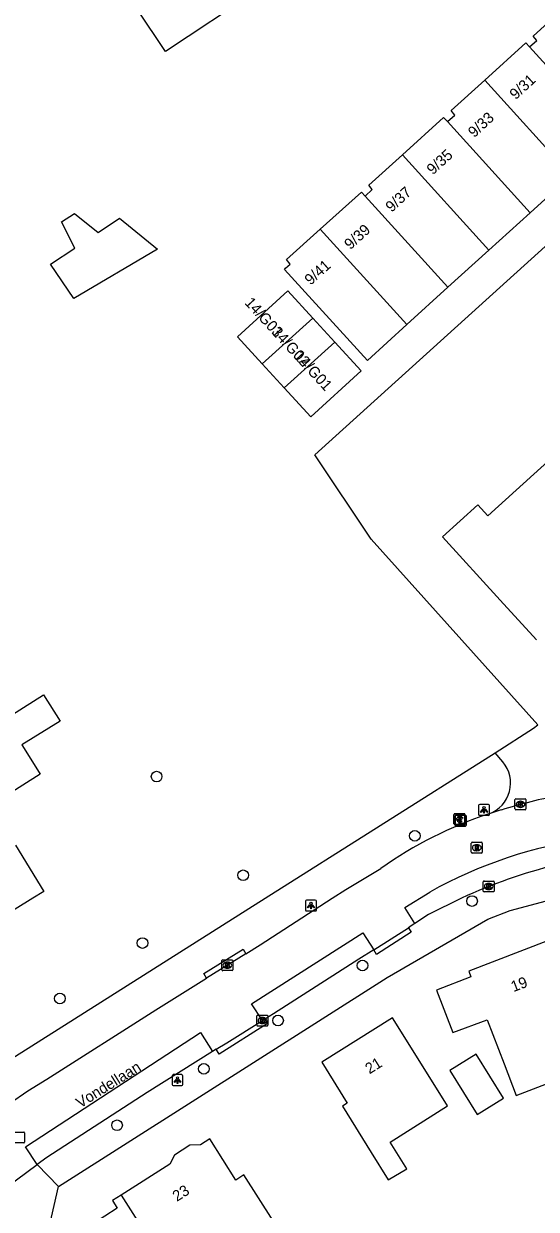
# Model space of a CAD drawing. Extents: x 161354 to 161876, y 382161 to 382804.
# Drawn here: x 161596.3 to 161643.4, y 382471.4 to 382580.4 of the extents above; entities that cross this region are included whole.
import ezdxf

# ---------------------------------------------------------------- set-up
doc = ezdxf.new("R2010")
doc.units = 0
for name, color, linetype in [('IMGEO_Betaalautomaat', 7, 'Continuous'), ('IMGEO_Boom', 7, 'Continuous'), ('IMGEO_Kolk', 7, 'Continuous'), ('IMGEO_Lichtpunt', 7, 'Continuous'), ('IMGEO_Openbare_ruimte_label', 7, 'Continuous'), ('IMGEO_Pand', 7, 'Continuous'), ('IMGEO_Pand_nummerreeks', 7, 'Continuous'), ('IMGEO_Pand_vergunning_verleend', 7, 'Continuous'), ('IMGEO_Parkeervlak_gesloten', 7, 'Continuous'), ('IMGEO_Rijbaan_lokaal_open', 7, 'Continuous'), ('IMGEO_Rioolput', 7, 'Continuous'), ('IMGEO_Voetpad_open', 7, 'Continuous')]:
    doc.layers.add(name, color=color, linetype=linetype)

msp = doc.modelspace()

# ---------------------------------------------------------------- linework, layer by layer
at = {"layer": 'IMGEO_Betaalautomaat'}
for p, q in [((161635.9, 382507.75), (161636.74, 382507.75)), ((161636.74, 382507.75), (161635.9, 382507.75)), ((161635.82, 382506.83), (161635.82, 382507.67)), ((161635.82, 382507.67), (161635.82, 382506.83)), ((161636.75, 382506.75), (161635.91, 382506.75)), ((161635.91, 382506.75), (161636.75, 382506.75)), ((161635.94, 382506.7), (161635.94, 382507.54)), ((161635.94, 382507.54), (161635.94, 382506.7)), ((161636.02, 382507.62), (161636.86, 382507.62)), ((161636.86, 382507.62), (161636.02, 382507.62)), ((161636.11, 382507.22), (161636.11, 382507.29)), ((161636.23, 382507.29), (161636.23, 382507.22)), ((161636.23, 382507.08), (161636.23, 382507.15)), ((161636.35, 382507.15), (161636.35, 382507.08)), ((161636.49, 382507.56), (161636.47, 382507.46)), ((161636.47, 382507.05), (161636.49, 382506.97)), ((161636.6, 382507.43), (161636.59, 382507.33)), ((161636.59, 382506.92), (161636.61, 382506.83)), ((161636.82, 382507.68), (161636.82, 382506.84)), ((161636.82, 382506.84), (161636.82, 382507.68)), ((161636.94, 382507.55), (161636.94, 382506.71)), ((161636.94, 382506.71), (161636.94, 382507.55)), ((161636.87, 382506.62), (161636.03, 382506.62)), ((161636.03, 382506.62), (161636.87, 382506.62))]:
    msp.add_line(p, q, dxfattribs=at)
for points in [[(161636.11, 382507.29), (161636.04, 382507.29), (161636.04, 382507.35), (161636.12, 382507.35)], [(161636.11, 382507.15), (161636.04, 382507.15), (161636.04, 382507.22), (161636.11, 382507.22)], [(161636.23, 382507.15), (161636.16, 382507.15), (161636.16, 382507.22), (161636.24, 382507.22)], [(161636.23, 382507.02), (161636.16, 382507.02), (161636.16, 382507.08), (161636.23, 382507.08)], [(161636.24, 382507.35), (161636.39, 382507.35), (161636.39, 382507.29), (161636.23, 382507.29)], [(161636.23, 382507.22), (161636.39, 382507.22), (161636.39, 382507.15), (161636.24, 382507.15)], [(161636.36, 382507.22), (161636.51, 382507.22), (161636.51, 382507.15), (161636.35, 382507.15)], [(161636.35, 382507.08), (161636.51, 382507.08), (161636.51, 382507.02), (161636.36, 382507.02)]]:
    msp.add_lwpolyline(points, dxfattribs=at)
for centre, radius, start, end in [((161635.9, 382507.68), 0.0779, 92.4484, 184.2845), ((161635.9, 382507.68), 0.0779, 92.4484, 184.2845), ((161636.75, 382507.68), 0.0779, 2.4484, 94.2845), ((161636.75, 382507.68), 0.0779, 2.4484, 94.2845), ((161635.9, 382506.83), 0.0779, 182.4484, 274.2845), ((161635.9, 382506.83), 0.0779, 182.4484, 274.2845), ((161636.02, 382507.54), 0.0779, 92.4484, 184.2845), ((161636.02, 382507.54), 0.0779, 92.4484, 184.2845), ((161636.02, 382506.7), 0.0779, 182.4484, 274.2845), ((161636.02, 382506.7), 0.0779, 182.4484, 274.2845), ((161636.37, 382507.2), 0.267, 191.8096, 297.0389), ((161636.4, 382507.28), 0.293, 73.014, 165.0139), ((161636.49, 382507.07), 0.267, 191.8096, 297.0389), ((161636.41, 382507.29), 0.179, 69.3236, 159.5683), ((161636.52, 382507.14), 0.293, 73.014, 165.0139), ((161636.41, 382507.22), 0.179, 202.7625, 291.8693), ((161636.53, 382507.16), 0.179, 69.3236, 159.5683), ((161636.53, 382507.08), 0.179, 202.7625, 291.8693), ((161636.75, 382506.83), 0.0779, 272.4484, 4.2845), ((161636.75, 382506.83), 0.0779, 272.4484, 4.2845), ((161636.86, 382507.54), 0.0779, 2.4484, 94.2845), ((161636.86, 382507.54), 0.0779, 2.4484, 94.2845), ((161636.86, 382506.7), 0.0779, 272.4484, 4.2845), ((161636.86, 382506.7), 0.0779, 272.4484, 4.2845)]:
    msp.add_arc(centre, radius, start, end, dxfattribs=at)
at = {"layer": 'IMGEO_Boom'}
for centre in [(161608.52, 382511.17), (161632.23, 382505.72), (161616.46, 382502.1), (161637.48, 382499.73), (161607.22, 382495.87), (161627.42, 382493.8), (161599.64, 382490.77), (161619.67, 382488.75), (161612.85, 382484.3), (161604.89, 382479.12)]:
    msp.add_circle(centre, 0.489, dxfattribs=at)
at = {"layer": 'IMGEO_Kolk'}
for p, q in [((161641.42, 382508.2), (161641.42, 382509.05)), ((161641.5, 382509.12), (161642.35, 382509.12)), ((161641.91, 382508.9), (161641.94, 382508.9)), ((161642.43, 382509.05), (161642.43, 382508.2)), ((161642.35, 382508.12), (161641.5, 382508.12)), ((161641.93, 382508.34), (161641.91, 382508.34)), ((161638.51, 382500.65), (161638.51, 382501.5)), ((161638.59, 382501.57), (161639.44, 382501.57)), ((161639, 382501.35), (161639.02, 382501.35)), ((161639.51, 382501.5), (161639.51, 382500.65)), ((161639.44, 382500.57), (161638.59, 382500.57)), ((161639.02, 382500.79), (161639, 382500.79)), ((161614.52, 382493.4), (161614.52, 382494.26)), ((161614.59, 382494.33), (161615.44, 382494.33)), ((161615, 382494.11), (161615.03, 382494.11)), ((161615.52, 382494.26), (161615.52, 382493.4)), ((161615.44, 382493.33), (161614.59, 382493.33)), ((161615.03, 382493.55), (161615, 382493.55)), ((161617.81, 382489.24), (161618.66, 382489.24)), ((161617.73, 382488.31), (161617.73, 382489.17)), ((161618.66, 382488.24), (161617.81, 382488.24)), ((161618.22, 382489.02), (161618.25, 382489.02)), ((161618.24, 382488.46), (161618.22, 382488.46)), ((161618.73, 382489.17), (161618.73, 382488.31))]:
    msp.add_line(p, q, dxfattribs=at)
for points in [[(161641.42, 382508.2), (161641.42, 382509.05)], [(161641.5, 382509.12), (161642.35, 382509.12)], [(161641.74, 382508.82), (161641.87, 382508.82), (161641.87, 382508.67), (161642, 382508.82), (161642.16, 382508.82), (161642.02, 382508.67), (161642.17, 382508.42), (161642.02, 382508.42), (161641.93, 382508.59), (161641.87, 382508.52), (161641.87, 382508.42), (161641.74, 382508.42), (161641.74, 382508.82)], [(161642.43, 382509.05), (161642.43, 382508.2)], [(161642.35, 382508.12), (161641.5, 382508.12)], [(161638.51, 382500.65), (161638.51, 382501.5)], [(161638.59, 382501.57), (161639.44, 382501.57)], [(161638.83, 382501.27), (161638.96, 382501.27), (161638.96, 382501.12), (161639.08, 382501.27), (161639.25, 382501.27), (161639.1, 382501.12), (161639.26, 382500.87), (161639.1, 382500.87), (161639.02, 382501.04), (161638.96, 382500.97), (161638.96, 382500.87), (161638.83, 382500.87), (161638.83, 382501.27)], [(161639.51, 382501.5), (161639.51, 382500.65)], [(161639.44, 382500.57), (161638.59, 382500.57)], [(161614.52, 382493.4), (161614.52, 382494.26)], [(161614.59, 382494.33), (161615.44, 382494.33)], [(161614.84, 382494.03), (161614.96, 382494.03), (161614.96, 382493.88), (161615.09, 382494.03), (161615.25, 382494.03), (161615.11, 382493.88), (161615.26, 382493.63), (161615.11, 382493.63), (161615.02, 382493.79), (161614.96, 382493.73), (161614.96, 382493.63), (161614.84, 382493.63), (161614.84, 382494.03)], [(161615.52, 382494.26), (161615.52, 382493.4)], [(161615.44, 382493.33), (161614.59, 382493.33)], [(161617.81, 382489.24), (161618.66, 382489.24)], [(161617.73, 382488.31), (161617.73, 382489.17)], [(161618.66, 382488.24), (161617.81, 382488.24)], [(161618.05, 382488.94), (161618.18, 382488.94), (161618.18, 382488.79), (161618.31, 382488.94), (161618.47, 382488.94), (161618.32, 382488.79), (161618.48, 382488.54), (161618.32, 382488.54), (161618.24, 382488.7), (161618.18, 382488.64), (161618.18, 382488.54), (161618.05, 382488.54), (161618.05, 382488.94)], [(161618.73, 382489.17), (161618.73, 382488.31)]]:
    msp.add_lwpolyline(points, dxfattribs=at)
for centre, start, end in [((161641.5, 382509.05), 91.552, 178.448), ((161641.5, 382509.05), 91.552, 178.448), ((161642.35, 382509.05), 1.552, 88.448), ((161642.35, 382509.05), 1.552, 88.448), ((161641.5, 382508.2), 181.552, 268.448), ((161641.5, 382508.2), 181.552, 268.448), ((161642.35, 382508.2), 271.552, 358.448), ((161642.35, 382508.2), 271.552, 358.448), ((161638.59, 382501.5), 91.552, 178.448), ((161638.59, 382501.5), 91.552, 178.448), ((161639.44, 382501.5), 1.552, 88.448), ((161639.44, 382501.5), 1.552, 88.448), ((161638.59, 382500.65), 181.552, 268.448), ((161638.59, 382500.65), 181.552, 268.448), ((161639.44, 382500.65), 271.552, 358.448), ((161639.44, 382500.65), 271.552, 358.448), ((161614.59, 382494.25), 91.552, 178.448), ((161614.59, 382494.25), 91.552, 178.448), ((161615.44, 382494.25), 1.552, 88.448), ((161615.44, 382494.25), 1.552, 88.448), ((161614.59, 382493.4), 181.552, 268.448), ((161614.59, 382493.4), 181.552, 268.448), ((161615.44, 382493.4), 271.552, 358.448), ((161615.44, 382493.4), 271.552, 358.448), ((161617.81, 382489.16), 91.552, 178.448), ((161617.81, 382489.16), 91.552, 178.448), ((161618.66, 382489.16), 1.552, 88.448), ((161618.66, 382489.16), 1.552, 88.448), ((161617.81, 382488.32), 181.552, 268.448), ((161617.81, 382488.32), 181.552, 268.448), ((161618.66, 382488.32), 271.552, 358.448), ((161618.66, 382488.32), 271.552, 358.448)]:
    msp.add_arc(centre, 0.0765, start, end, dxfattribs=at)
for centre, major_axis, ratio, start_param, end_param in [((161641.91, 382508.62), (-0.387, 0.002), 0.722429, 4.712389, 7.853982), ((161641.94, 382508.62), (-0.39, 0.002), 0.717154, 1.570796, 4.712389), ((161639, 382501.07), (-0.387, 0.002), 0.722429, 4.712389, 7.853982), ((161639.02, 382501.07), (-0.39, 0.002), 0.717154, 1.570796, 4.712389), ((161615, 382493.83), (-0.387, 0.002), 0.722429, 4.712389, 7.853982), ((161615.03, 382493.83), (-0.39, 0.002), 0.717154, 1.570796, 4.712389), ((161618.22, 382488.74), (-0.387, 0.002), 0.722429, 4.712389, 7.853982), ((161618.24, 382488.74), (-0.39, 0.002), 0.717154, 1.570796, 4.712389)]:
    msp.add_ellipse(centre, major_axis=major_axis, ratio=ratio, start_param=start_param, end_param=end_param, dxfattribs=at)
at = {"layer": 'IMGEO_Lichtpunt'}
for p, q in [((161638.08, 382508.51), (161638.08, 382507.7)), ((161638.08, 382508.51), (161638.08, 382507.7)), ((161638.98, 382508.6), (161638.18, 382508.6)), ((161638.98, 382508.6), (161638.18, 382508.6)), ((161639.08, 382507.7), (161639.08, 382508.51)), ((161639.08, 382507.7), (161639.08, 382508.51)), ((161638.18, 382507.61), (161638.98, 382507.61)), ((161638.18, 382507.61), (161638.98, 382507.61)), ((161622.19, 382499.72), (161622.19, 382498.91)), ((161622.19, 382499.72), (161622.19, 382498.91)), ((161623.09, 382499.82), (161622.28, 382499.82)), ((161623.09, 382499.82), (161622.28, 382499.82)), ((161623.19, 382498.91), (161623.19, 382499.72)), ((161623.19, 382498.91), (161623.19, 382499.72)), ((161622.28, 382498.82), (161623.09, 382498.82)), ((161622.28, 382498.82), (161623.09, 382498.82)), ((161610.84, 382483.77), (161610.03, 382483.77)), ((161610.84, 382483.77), (161610.03, 382483.77)), ((161609.94, 382483.67), (161609.94, 382482.87)), ((161609.94, 382483.67), (161609.94, 382482.87)), ((161610.03, 382482.77), (161610.84, 382482.77)), ((161610.03, 382482.77), (161610.84, 382482.77)), ((161610.93, 382482.87), (161610.93, 382483.67)), ((161610.93, 382482.87), (161610.93, 382483.67))]:
    msp.add_line(p, q, dxfattribs=at)
for points in [[(161638.46, 382508.17), (161638.49, 382508.15), (161638.31, 382507.88), (161638.27, 382507.91), (161638.46, 382508.17)], [(161638.56, 382508.13), (161638.6, 382508.13), (161638.6, 382507.8), (161638.56, 382507.8), (161638.56, 382508.13)], [(161638.67, 382508.15), (161638.71, 382508.17), (161638.89, 382507.91), (161638.85, 382507.88), (161638.67, 382508.15)], [(161622.56, 382499.38), (161622.6, 382499.36), (161622.42, 382499.09), (161622.38, 382499.12), (161622.56, 382499.38)], [(161622.67, 382499.34), (161622.71, 382499.34), (161622.71, 382499.01), (161622.67, 382499.01), (161622.67, 382499.34)], [(161622.78, 382499.36), (161622.81, 382499.38), (161623, 382499.12), (161622.96, 382499.09), (161622.78, 382499.36)], [(161610.31, 382483.34), (161610.35, 382483.31), (161610.16, 382483.05), (161610.12, 382483.07), (161610.31, 382483.34)], [(161610.41, 382483.29), (161610.46, 382483.29), (161610.46, 382482.97), (161610.41, 382482.97), (161610.41, 382483.29)], [(161610.52, 382483.31), (161610.56, 382483.34), (161610.75, 382483.07), (161610.71, 382483.05), (161610.52, 382483.31)]]:
    msp.add_lwpolyline(points, dxfattribs=at)
for centre in [(161638.58, 382508.31), (161622.69, 382499.52), (161610.44, 382483.47)]:
    msp.add_circle(centre, 0.0994, dxfattribs=at)
for centre, start, end in [((161638.18, 382508.51), 90, 180), ((161638.18, 382508.51), 90, 180), ((161638.98, 382508.51), 0, 90), ((161638.98, 382508.51), 0, 90), ((161638.18, 382507.7), 180, 270), ((161638.18, 382507.7), 180, 270), ((161638.98, 382507.7), 270, 0), ((161638.98, 382507.7), 270, 360), ((161622.28, 382499.72), 90, 180), ((161622.28, 382499.72), 90, 180), ((161623.09, 382499.72), 0, 90), ((161623.09, 382499.72), 0, 90), ((161622.28, 382498.91), 180, 270), ((161622.28, 382498.91), 180, 270), ((161623.09, 382498.91), 270, 0), ((161623.09, 382498.91), 270, 360), ((161610.03, 382483.67), 90, 180), ((161610.03, 382483.67), 90, 180), ((161610.84, 382483.67), 0, 90), ((161610.84, 382483.67), 0, 90), ((161610.03, 382482.87), 180, 270), ((161610.03, 382482.87), 180, 270), ((161610.84, 382482.87), 270, 0), ((161610.84, 382482.87), 270, 360)]:
    msp.add_arc(centre, 0.0946, start, end, dxfattribs=at)
at = {"layer": 'IMGEO_Pand'}
for points in [[(161617.74, 382583.42), (161609.32, 382577.81), (161601.47, 382589.62)], [(161642.76, 382578.24), (161643.43, 382578.83), (161643.1, 382579.23), (161646.19, 382582.04)], [(161638.64, 382575.19), (161642.41, 382578.62), (161642.76, 382578.24)], [(161650.36, 382569.86), (161642.76, 382578.24)], [(161635.21, 382571.38), (161635.89, 382571.98), (161635.56, 382572.39), (161638.64, 382575.19)], [(161638.64, 382575.19), (161646.58, 382566.43)], [(161631.09, 382568.33), (161634.86, 382571.76), (161635.21, 382571.38)], [(161642.81, 382563), (161635.21, 382571.38)], [(161627.66, 382564.52), (161628.32, 382565.12), (161627.99, 382565.52), (161631.09, 382568.33)], [(161639.03, 382559.57), (161631.09, 382568.33)], [(161674.64, 382567.53), (161638.94, 382535.13), (161638.01, 382536.16), (161634.76, 382533.21), (161640.06, 382527.37), (161643.39, 382523.73)], [(161646.58, 382566.43), (161642.81, 382563)], [(161623.53, 382561.48), (161627.32, 382564.9), (161627.66, 382564.52)], [(161635.26, 382556.15), (161627.66, 382564.52)], [(161642.81, 382563), (161639.03, 382559.57)], [(161631.48, 382552.71), (161627.87, 382549.43), (161620.25, 382557.79), (161620.36, 382557.89), (161620.78, 382558.27), (161620.45, 382558.7), (161623.53, 382561.48)], [(161631.48, 382552.71), (161623.53, 382561.48)], [(161639.03, 382559.57), (161635.26, 382556.15)], [(161618.22, 382549.12), (161615.95, 382551.6), (161620.57, 382555.83), (161622.87, 382553.31)], [(161635.26, 382556.15), (161631.48, 382552.71)], [(161622.87, 382553.31), (161618.22, 382549.12)], [(161622.87, 382553.31), (161624.89, 382551.1)], [(161624.89, 382551.1), (161627.3, 382548.48), (161622.68, 382544.25), (161620.24, 382546.91)], [(161620.24, 382546.91), (161624.89, 382551.1)], [(161620.24, 382546.91), (161618.22, 382549.12)], [(161588.47, 382525.14), (161594.1, 382516.15), (161598.14, 382518.68), (161599.65, 382516.26), (161596.15, 382514.08)], [(161596.15, 382514.08), (161596.37, 382513.74), (161597.84, 382511.38), (161592.68, 382508.15)], [(161595.57, 382504.88), (161598.18, 382500.62), (161597.17, 382500), (161593.88, 382497.98)], [(161645.12, 382483.24), (161645.64, 382483.44), (161645.81, 382483.51), (161645.97, 382483.1), (161649.52, 382484.47), (161648.04, 382488.31), (161647.84, 382488.23), (161646.43, 382491.89), (161649.3, 382492.99), (161647.85, 382496.77), (161644.62, 382495.52), (161644.41, 382496.06), (161637.17, 382493.28), (161637.37, 382492.75), (161634.22, 382491.54), (161635.71, 382487.65), (161638.86, 382488.81), (161640.42, 382484.76), (161641.53, 382481.86), (161645.12, 382483.24)], [(161632.83, 382484.73), (161630.19, 382488.98), (161623.68, 382484.93), (161626.02, 382481.16), (161625.57, 382480.88), (161628.21, 382476.63), (161629.77, 382474.11), (161631.49, 382475.11), (161629.95, 382477.58), (161635.23, 382480.91), (161632.83, 382484.73)], [(161635.45, 382484.14), (161637.95, 382480.1), (161640.38, 382481.61), (161637.87, 382485.64), (161635.45, 382484.14)], [(161619.13, 382465.69), (161623.02, 382464.82), (161623.73, 382468.01), (161620.2, 382468.79), (161619.22, 382470.34), (161616.54, 382474.55), (161615.79, 382474.08), (161613.39, 382477.86), (161612.54, 382477.32), (161611.58, 382477.28), (161610.17, 382476.38), (161609.73, 382475.54), (161605.26, 382472.7)], [(161605.26, 382472.7), (161604.46, 382472.19), (161604.91, 382471.49), (161602.62, 382470.03), (161601.24, 382463.88), (161602.74, 382461.53), (161601.96, 382461.04), (161603.69, 382458.32)], [(161605.26, 382472.7), (161607.62, 382468.98), (161612.38, 382467.44)]]:
    msp.add_lwpolyline(points, dxfattribs=at)
at = {"layer": 'IMGEO_Pand_vergunning_verleend'}
msp.add_lwpolyline([(161598.79, 382558.26), (161601.01, 382559.74), (161599.78, 382562.17), (161600.97, 382562.94), (161603.15, 382561.19), (161605.1, 382562.51), (161608.6, 382559.65), (161600.91, 382555.11), (161598.79, 382558.26)], dxfattribs=at)
at = {"layer": 'IMGEO_Parkeervlak_gesloten'}
msp.add_lwpolyline([(161643.53, 382515.94), (161628.21, 382532.98), (161623.05, 382540.75), (161664.71, 382578.47)], dxfattribs=at)
at = {"layer": 'IMGEO_Rijbaan_lokaal_open'}
for points in [[(161640.15, 382508.1), (161639.04, 382507.75)], [(161616.72, 382494.89), (161618.03, 382495.71), (161624.65, 382500), (161625.9, 382500.8), (161629.11, 382502.73)], [(161632.24, 382497.67), (161631.3, 382499.14), (161633.6, 382500.56)], [(161628.45, 382495.24), (161631.64, 382497.28)], [(161632.24, 382497.67), (161631.89, 382497.44), (161631.64, 382497.28)], [(161618.23, 382488.74), (161617.23, 382490.29), (161627.44, 382496.82), (161628.45, 382495.24)], [(161616.72, 382494.89), (161613.11, 382492.65)], [(161595, 382481.12), (161596.7, 382482.28), (161598.44, 382483.37), (161608.44, 382489.73), (161613.11, 382492.65)], [(161614, 382486.1), (161614.96, 382486.71), (161618.23, 382488.74)], [(161597.56, 382475.51), (161596.49, 382477.14), (161612.56, 382487.64), (161613.66, 382485.89)], [(161614, 382486.1), (161613.66, 382485.89)], [(161593.85, 382472.77), (161597.56, 382475.51)]]:
    msp.add_lwpolyline(points, dxfattribs=at)
for centre, radius, start, end in [((161652.59, 382469.19), 40.84, 99.815, 107.7247), ((161650.81, 382472.1), 37.54, 108.2819, 125.3272), ((161653.89, 382464.23), 41.61, 97.7606, 119.1819)]:
    msp.add_arc(centre, radius, start, end, dxfattribs=at)
at = {"layer": 'IMGEO_Rioolput'}
for p, q in [((161637.41, 382504.21), (161637.41, 382505.06)), ((161637.49, 382505.13), (161638.34, 382505.13)), ((161637.9, 382504.91), (161637.93, 382504.91)), ((161638.42, 382505.06), (161638.42, 382504.21)), ((161638.34, 382504.13), (161637.49, 382504.13)), ((161637.92, 382504.35), (161637.9, 382504.35)), ((161595.47, 382478.49), (161596.32, 382478.49)), ((161596.39, 382478.42), (161596.39, 382477.57)), ((161596.32, 382477.49), (161595.47, 382477.49))]:
    msp.add_line(p, q, dxfattribs=at)
for points in [[(161637.41, 382504.21), (161637.41, 382505.06)], [(161637.49, 382505.13), (161638.34, 382505.13)], [(161638, 382504.83), (161637.75, 382504.83), (161637.75, 382504.43)], [(161637.75, 382504.43), (161637.88, 382504.43), (161637.88, 382504.6), (161637.89, 382504.6)], [(161637.93, 382504.75), (161637.88, 382504.75), (161637.88, 382504.67)], [(161637.88, 382504.67), (161637.93, 382504.67)], [(161637.93, 382504.57), (161638, 382504.43), (161638.14, 382504.43), (161638.08, 382504.56)], [(161638.42, 382505.06), (161638.42, 382504.21)], [(161638.34, 382504.13), (161637.49, 382504.13)], [(161595.47, 382478.49), (161596.32, 382478.49)], [(161596.39, 382478.42), (161596.39, 382477.57)], [(161596.32, 382477.49), (161595.47, 382477.49)]]:
    msp.add_lwpolyline(points, dxfattribs=at)
for centre, radius, start, end in [((161637.49, 382505.06), 0.0765, 91.552, 178.448), ((161637.49, 382505.06), 0.0765, 91.552, 178.448), ((161637.88, 382504.54), 0.0533, 26.0293, 88.6989), ((161637.93, 382504.66), 0.0964, 77.0061, 93.1865), ((161637.91, 382504.86), 0.19, 274.7715, 282.9687), ((161637.95, 382504.71), 0.0378, 276.6634, 79.6772), ((161638, 382504.72), 0.109, 350.3612, 89.416), ((161638, 382504.72), 0.112, 277.5842, 350.9817), ((161637.98, 382504.51), 0.108, 29.5134, 73.7905), ((161638.34, 382505.06), 0.0765, 1.552, 88.448), ((161638.34, 382505.06), 0.0765, 1.552, 88.448), ((161637.49, 382504.21), 0.0765, 181.552, 268.448), ((161637.49, 382504.21), 0.0765, 181.552, 268.448), ((161638.34, 382504.21), 0.0765, 271.552, 358.448), ((161638.34, 382504.21), 0.0765, 271.552, 358.448), ((161596.32, 382478.42), 0.0765, 1.552, 88.448), ((161596.32, 382478.42), 0.0765, 1.552, 88.448), ((161596.32, 382477.57), 0.0765, 271.552, 358.448), ((161596.32, 382477.57), 0.0765, 271.552, 358.448)]:
    msp.add_arc(centre, radius, start, end, dxfattribs=at)
for centre, major_axis, ratio, start_param, end_param in [((161637.9, 382504.63), (-0.387, 0.002), 0.722429, 4.712389, 7.853982), ((161637.93, 382504.63), (-0.39, 0.002), 0.717154, 1.570796, 4.712389)]:
    msp.add_ellipse(centre, major_axis=major_axis, ratio=ratio, start_param=start_param, end_param=end_param, dxfattribs=at)
at = {"layer": 'IMGEO_Voetpad_open'}
for points in [[(161639.59, 382513.36), (161643.13, 382515.61), (161643.53, 382515.94)], [(161593.11, 382483.94), (161618.48, 382500), (161639.59, 382513.36)], [(161640.29, 382512.53), (161639.59, 382513.36)], [(161599.51, 382473.49), (161629.7, 382492.69), (161638.92, 382498.07), (161640.97, 382498.87), (161645.24, 382500), (161645.36, 382500.03)], [(161636.5, 382500), (161633.49, 382498.5), (161632.24, 382497.67)], [(161631.64, 382497.28), (161631.9, 382496.88), (161628.71, 382494.83), (161628.45, 382495.24)], [(161613.11, 382492.65), (161612.86, 382493.07), (161616.46, 382495.32), (161616.72, 382494.89)], [(161628.45, 382495.24), (161627.1, 382494.38), (161619.24, 382489.36), (161618.45, 382488.87)], [(161618.45, 382488.87), (161618.71, 382488.46), (161614.27, 382485.66), (161614, 382486.1)], [(161618.45, 382488.87), (161618.23, 382488.74)], [(161613.66, 382485.89), (161607.66, 382482.13), (161598.45, 382476.17), (161597.56, 382475.51)], [(161597.56, 382475.51), (161599.51, 382473.49)], [(161606.6, 382446.2), (161596.87, 382461.93), (161599.51, 382473.49)]]:
    msp.add_lwpolyline(points, dxfattribs=at)
for centre, radius, start, end in [((161638.02, 382510.57), 3, 289.8968, 40.6633), ((161657.63, 382453.85), 50.75, 104.1279, 114.6068)]:
    msp.add_arc(centre, radius, start, end, dxfattribs=at)

# ---------------------------------------------------------------- texts
at = {"layer": 'IMGEO_Openbare_ruimte_label'}
msp.add_text('Vondellaan', height=1, rotation=32.0054, dxfattribs=at).set_placement((161601.51, 382480.66))
at = {"layer": 'IMGEO_Pand_nummerreeks'}
for s, rotation, p in [('9/31', 42.3174, (161641.48, 382573.34)), ('9/33', 42.5253, (161637.67, 382569.85)), ('9/35', 42.2652, (161633.87, 382566.43)), ('9/37', 42.3267, (161630.09, 382562.99)), ('9/39', 42.1705, (161626.3, 382559.55)), ('9/41', 41.7927, (161622.65, 382556.29)), ('14/G03', 312.4846, (161616.54, 382554.68)), ('14/G02', 312.4842, (161619.01, 382551.98)), ('14/G01', 312.4846, (161621.04, 382549.77)), ('19', 21.0218, (161641.28, 382491.35)), ('21', 31.8811, (161628.06, 382483.79)), ('23', 32.4122, (161610.38, 382472.07))]:
    msp.add_text(s, height=1, rotation=rotation, dxfattribs=at).set_placement(p)

doc.saveas('drawing.dxf')
